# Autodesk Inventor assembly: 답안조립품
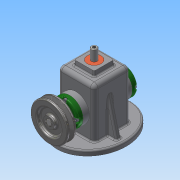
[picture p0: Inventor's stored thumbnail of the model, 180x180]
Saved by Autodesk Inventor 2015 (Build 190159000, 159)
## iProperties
Created: 2017-07
Part Number: 답안조립품
Document SubType Name: Assembly
Designer: owner
Author: owner
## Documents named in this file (15)
- C:\Users\owner\Desktop\470707V1010\답안조립품.iam
- C:\Users\owner\Desktop\470707V1010\본체.ipt
- C:\Users\owner\Desktop\470707V1010\편심축.ipt
- C:\Users\owner\Desktop\470707V1010\링크.ipt
- C:\Users\owner\Desktop\470707V1010\베어링 12 x 32 x 10.ipt
- C:\Users\owner\Desktop\470707V1010\앞커버.ipt
- C:\Users\owner\Desktop\470707V1010\볼트 M4 x 12.ipt
- C:\Users\owner\Desktop\470707V1010\뒤커버.ipt
- C:\Users\owner\Desktop\470707V1010\오일실 12 25 7.ipt
- C:\Users\owner\Desktop\470707V1010\슬라이드.ipt
- C:\Users\owner\Desktop\470707V1010\핀 5 x 18.ipt
- C:\Users\owner\Desktop\470707V1010\부시.ipt
- C:\Users\owner\Desktop\470707V1010\키 4 x 4 x 10.ipt
- C:\Users\owner\Desktop\470707V1010\V벨트풀리.ipt
- C:\Users\owner\Desktop\470707V1010\고정핀 1.2 x  8.ipt
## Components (3 placed, 3 different names)
1. 핀 5 x 18:1 — 각도:1
2. V벨트풀리:1 — 각도:3
3. 고정핀 1.2 x  8:1
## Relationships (2: Angle 2)
- 각도:1 [Angle]: 핀 5 x 18:1
- 각도:3 [Angle]: V벨트풀리:1
